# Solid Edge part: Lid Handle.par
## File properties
Username: m_hel
Author: m_hel
Template: Iso Metric Part.par
Last saved by: m_hel
Revision: 4
Application: Solid Edge
Accuracy: 0,990
Material: Chrome
Face Style: Chrome
Fill Style: Normal
Virtual Style: Normal
Grouping: Uncategorized
LibraryName: Custom Materials
Coef. of Thermal Exp: 0.0
Thermal Conductivity: 0.0
Specific Heat: 0.0
Modulus of Elasticity: 0.0
Poisson's Ratio: 0.0
Yield Stress: 0.0
Ultimate Stress: 0.0
Elongation: 0.0
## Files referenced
..\Lid Handle.asm
G:\OneDriveTemp\OneDrive\Dokumendid\TLÜ tööd\3D Modelleerimine\3d modelling\veesõiduk\Lids\Lid Handle Base.psm
iduk\Lids\Lid Handle Base.psm
iduk\Lids\Lid Handle.asm
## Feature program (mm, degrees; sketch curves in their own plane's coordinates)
sketch for "unnamed Protrusion 1" plane through (0, 0, 0) normal (0, 0, 1) x-axis (1, 0, 0)
  line (8, -25.2982) -> (8, -12.2)
  arc centre (12.2, -12.2) radius 4.2 from (8, -12.2) to (12.2, -8) cw
  line (12.2, -8) -> (25.2982, -8)
  arc centre (25.2982, -6) radius 2 from (25.2982, -8) to (27.2442, -6.4615) ccw
  arc centre (0, 0) radius 28 from (27.2442, -6.4615) to (-27.2442, -6.4615) ccw
  arc centre (-25.2982, -6) radius 2 from (-27.2442, -6.4615) to (-25.2982, -8) ccw
  line (-25.2982, -8) -> (-12.2, -8)
  arc centre (-12.2, -12.2) radius 4.2 from (-12.2, -8) to (-8, -12.2) cw
  line (-8, -12.2) -> (-8, -25.2982)
  arc centre (-6, -25.2982) radius 2 from (-8, -25.2982) to (-6.4615, -27.2442) ccw
  arc centre (0, 0) radius 28 from (-6.4615, -27.2442) to (6.4615, -27.2442) ccw
  arc centre (6, -25.2982) radius 2 from (6.4615, -27.2442) to (8, -25.2982) ccw
extrude "unnamed Protrusion 1" add finite 10 along -normal
sketch for "unnamed Cutout 1" plane through (0, 0, 0) normal (0, 0, 1) x-axis (0, 1, 0)
  arc centre (0, 0) radius 21 from (-1, -20.9762) to (-1, 20.9762) ccw
  line (-1, 20.9762) -> (-1, -20.9762)
extrude "unnamed Cutout 1" cut through along -normal
fillet "Round_1" radius 2
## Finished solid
Body 1: solid body, 44 faces, 90 edges, 48 vertices.
  Faces by surface: cylinder 19, torus 10, sphere 8, plane 7
  Edges by curve: circle 52, line 34, intersection 4
Bounding box of the edges (mm; curved faces can reach further): 56.000 x 56.000 x 10.000, from (-28, -28, -10) to (28, 28, 0).
Cylindrical faces by radius (mm): R2 x14, R4.2 x2, R21 x1, R28 x2
Toroidal faces (ring radius, tube radius in mm): R6.2 r2 x4, R23 r2 x2, R26 r2 x4
Spherical faces by radius (mm): R2 x8
Planar faces by outward normal: +x 1, +y 1, +z 1, -x 1, -y 2, -z 1
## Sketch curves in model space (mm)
line (-20.9762, -1, 0) -> (20.9762, -1, 0)
arc centre (0, 0, 0) radius 21 from (20.9762, -1, 0) through (0, 21, 0) to (-20.9762, -1, 0)
arc centre (25.2982, -6, 0) radius 2 from (25.2982, -8, 0) through (26.5837, -7.5322, 0) to (27.2442, -6.4615, 0)
arc centre (0, 0, 0) radius 28 from (27.2442, -6.4615, 0) through (-2.4805, 27.8899, 0) to (-27.2442, -6.4615, 0)
arc centre (-25.2982, -6, 0) radius 2 from (-27.2442, -6.4615, 0) through (-26.4924, -7.6043, 0) to (-25.2982, -8, 0)
line (-25.2982, -8, 0) -> (-12.2, -8, 0)
arc centre (-12.2, -12.2, 0) radius 4.2 from (-12.2, -8, 0) through (-9.145, -9.3178, 0) to (-8, -12.2, 0)
line (-8, -12.2, 0) -> (-8, -25.2982, 0)
arc centre (-6, -25.2982, 0) radius 2 from (-8, -25.2982, 0) through (-7.5322, -26.5837, 0) to (-6.4615, -27.2442, 0)
arc centre (0, 0, 0) radius 28 from (-6.4615, -27.2442, 0) through (0, -28, 0) to (6.4615, -27.2442, 0)
arc centre (6, -25.2982, 0) radius 2 from (6.4615, -27.2442, 0) through (7.6043, -26.4924, 0) to (8, -25.2982, 0)
line (8, -25.2982, 0) -> (8, -12.2, 0)
arc centre (12.2, -12.2, 0) radius 4.2 from (8, -12.2, 0) through (9.3178, -9.145, 0) to (12.2, -8, 0)
line (12.2, -8, 0) -> (25.2982, -8, 0)
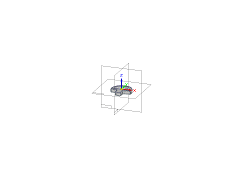
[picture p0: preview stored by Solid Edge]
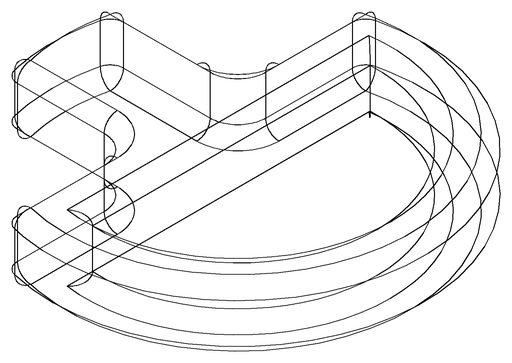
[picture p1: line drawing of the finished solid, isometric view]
